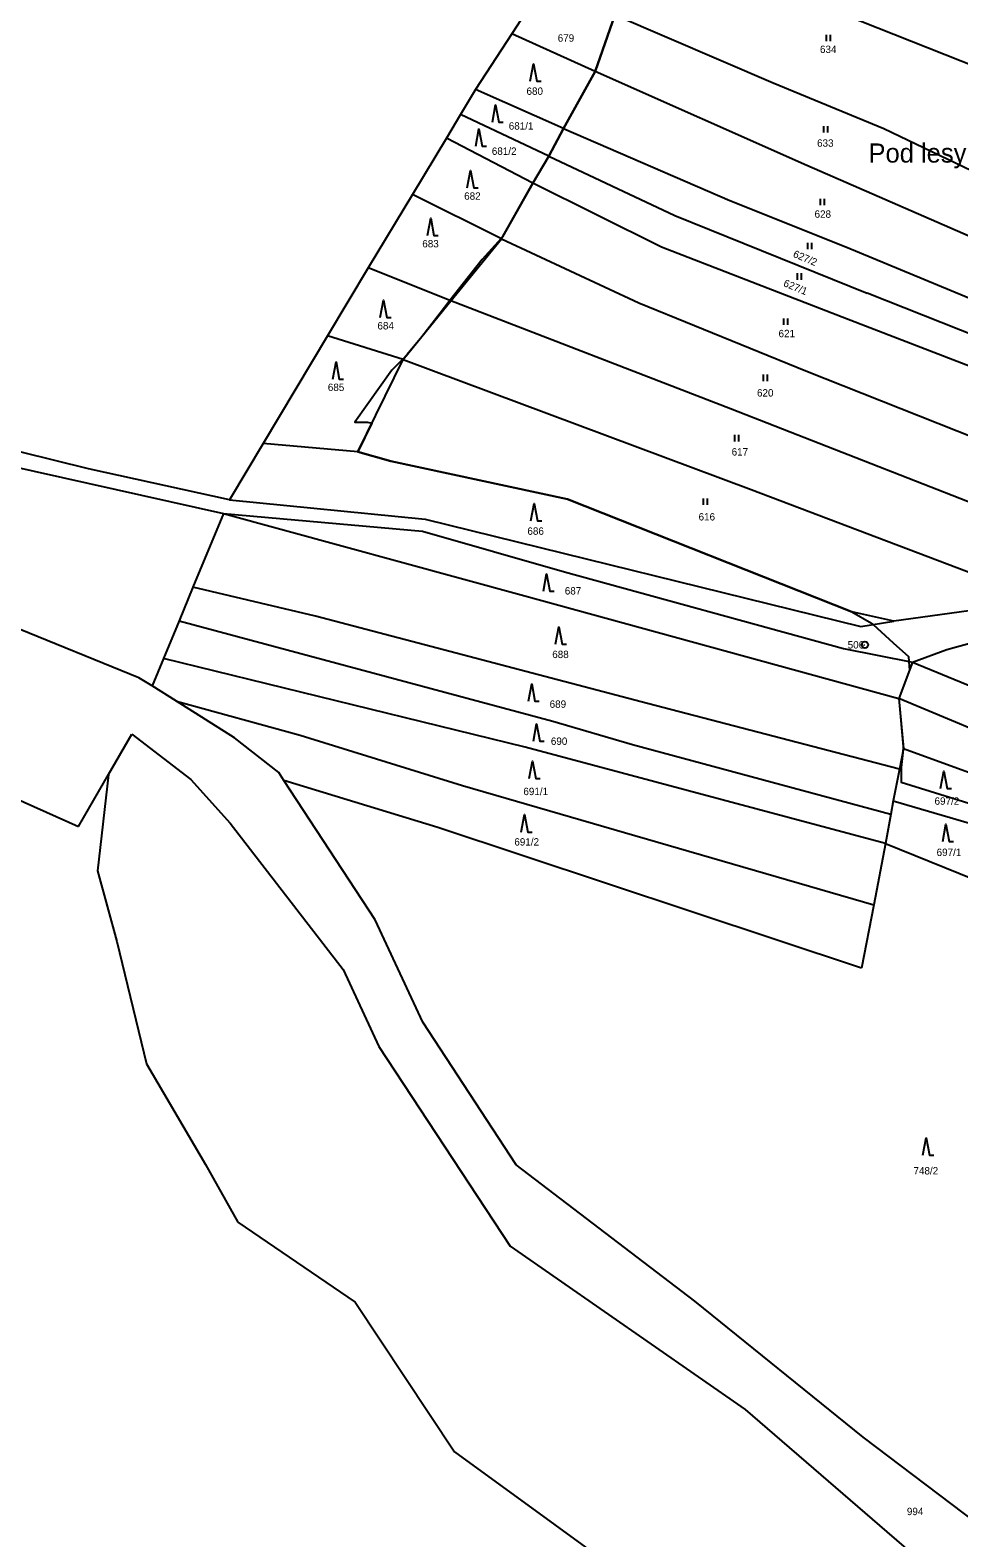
# Model space of a CAD drawing. Extents: x -749173 to -746119, y -1132678 to -1130338.
# Drawn here: x -748921.4 to -748707.5, y -1131207.1 to -1130859.8 of the extents above; entities that cross this region are included whole.
import ezdxf

# ---------------------------------------------------------------- set-up
doc = ezdxf.new("R2010")
doc.units = 0
for name, color, linetype in [('Vrstva 1', 7, 'Continuous'), ('Vrstva 15', 7, 'Continuous'), ('Vrstva 17', 7, 'Continuous'), ('Vrstva 18', 7, 'Continuous'), ('Vrstva 24', 7, 'Continuous'), ('Vrstva 25', 7, 'Continuous'), ('Vrstva 52', 7, 'Continuous'), ('Vrstva 6', 7, 'Continuous')]:
    doc.layers.add(name, color=color, linetype=linetype)

msp = doc.modelspace()

# ---------------------------------------------------------------- linework, layer by layer
at = {"layer": 'Vrstva 1'}
for points in [[(-748802.84, -1130848.91), (-748810.46, -1130860.65)], [(-748791.23, -1130869.37), (-748786.7, -1130856.35)], [(-748810.46, -1130860.65), (-748818.81, -1130873.52)], [(-748798.57, -1130882.46), (-748791.23, -1130869.37)], [(-748818.81, -1130873.52), (-748822.26, -1130879.25)], [(-748822.26, -1130879.25), (-748825.52, -1130884.67)], [(-748801.95, -1130888.88), (-748798.57, -1130882.46)], [(-748825.52, -1130884.67), (-748833.33, -1130897.65)], [(-748805.64, -1130895.06), (-748801.95, -1130888.88)], [(-748833.33, -1130897.65), (-748843.53, -1130914.6)], [(-748812.83, -1130907.88), (-748805.64, -1130895.06)], [(-748824.49, -1130922.2), (-748812.83, -1130907.88)], [(-748843.53, -1130914.6), (-748852.94, -1130930.24)], [(-748835.48, -1130935.7), (-748824.49, -1130922.2)], [(-748852.94, -1130930.24), (-748867.73, -1130955.03)], [(-748845.89, -1130956.91), (-748835.48, -1130935.7)], [(-748907.96, -1130960.85), (-748977.23, -1130943.74)], [(-748867.73, -1130955.03), (-748875.49, -1130968.04)], [(-748838.31, -1130959.08), (-748845.89, -1130956.91)], [(-748932.91, -1130958.6), (-748876.9, -1130971.17)], [(-748797.6, -1130967.82), (-748838.31, -1130959.08)], [(-748875.49, -1130968.04), (-748907.96, -1130960.85)], [(-748875.49, -1130968.04), (-748830.4, -1130972.44)], [(-748732.08, -1130993.78), (-748797.6, -1130967.82)], [(-748876.9, -1130971.17), (-748831.06, -1130975.19)], [(-748830.4, -1130972.44), (-748730.06, -1130997.2)], [(-748831.06, -1130975.19), (-748798.34, -1130984.6)], [(-748798.34, -1130984.6), (-748734.03, -1131002.28)], [(-748687.86, -1130991.16), (-748722.45, -1130995.95)], [(-748722.45, -1130995.95), (-748732.08, -1130993.78)], [(-748896.35, -1131008.97), (-748925.75, -1130997.04)], [(-748730.06, -1130997.2), (-748722.45, -1130995.95)], [(-748710.23, -1131002.5), (-748691.81, -1130997.44)], [(-748734.03, -1131002.28), (-748718.11, -1131005.41)], [(-748718.11, -1131005.41), (-748721.27, -1131013.77)], [(-748718.11, -1131005.41), (-748710.23, -1131002.5)], [(-748893.32, -1131010.83), (-748896.35, -1131008.97)], [(-748887.67, -1131014.39), (-748893.32, -1131010.83)], [(-748874.3, -1131022.82), (-748887.67, -1131014.39)], [(-748721.27, -1131013.77), (-748720.21, -1131025.25)], [(-748903.36, -1131031.29), (-748897.97, -1131021.96)], [(-748897.97, -1131021.96), (-748884.41, -1131032.45)], [(-748864.13, -1131030.78), (-748874.3, -1131022.82)], [(-748720.21, -1131025.25), (-748699.34, -1131032.91)], [(-748945.65, -1131027.42), (-748910.29, -1131043.26)], [(-748910.29, -1131043.26), (-748903.36, -1131031.29)], [(-748884.41, -1131032.45), (-748875.35, -1131042.49)], [(-748862.93, -1131032.61), (-748864.13, -1131030.78)], [(-748841.96, -1131064.7), (-748862.93, -1131032.61)], [(-748875.35, -1131042.49), (-748849.27, -1131076.16)], [(-748830.94, -1131088.32), (-748841.96, -1131064.7)], [(-748849.27, -1131076.16), (-748841.05, -1131093.93)], [(-748809.47, -1131121.13), (-748830.94, -1131088.32)], [(-748841.05, -1131093.93), (-748810.83, -1131139.93)], [(-748768.27, -1131152.58), (-748809.47, -1131121.13)], [(-748810.83, -1131139.93), (-748756.69, -1131177.5)], [(-748729.51, -1131183.85), (-748768.27, -1131152.58)], [(-748756.69, -1131177.5), (-748711.66, -1131216.37)], [(-748683.15, -1131218.97), (-748729.51, -1131183.85)]]:
    msp.add_lwpolyline(points, dxfattribs=at)
at = {"layer": 'Vrstva 24'}
msp.add_line((-748729.19, -1131001.4), (-748729.09, -1131001.4), dxfattribs=at)
msp.add_circle((-748729.14, -1131001.4), 0.756, dxfattribs=at)
at = {"layer": 'Vrstva 25'}
for p, q in [((-748738.05, -1130860.89), (-748738.05, -1130862.39)), ((-748737.05, -1130862.39), (-748737.05, -1130860.89)), ((-748738.64, -1130881.91), (-748738.64, -1130883.41)), ((-748737.64, -1130883.41), (-748737.64, -1130881.91)), ((-748739.41, -1130898.66), (-748739.41, -1130900.16)), ((-748738.41, -1130900.16), (-748738.41, -1130898.66)), ((-748742.3, -1130908.79), (-748742.3, -1130910.29)), ((-748741.3, -1130910.29), (-748741.3, -1130908.79)), ((-748744.71, -1130915.83), (-748744.71, -1130917.33)), ((-748743.71, -1130917.33), (-748743.71, -1130915.83)), ((-748747.86, -1130926.23), (-748747.86, -1130927.73)), ((-748746.86, -1130927.73), (-748746.86, -1130926.23)), ((-748752.55, -1130939.14), (-748752.55, -1130940.64)), ((-748751.55, -1130940.64), (-748751.55, -1130939.14)), ((-748759.11, -1130953.03), (-748759.11, -1130954.53)), ((-748758.11, -1130954.53), (-748758.11, -1130953.03)), ((-748766.4, -1130967.68), (-748766.4, -1130969.18)), ((-748765.4, -1130969.18), (-748765.4, -1130967.68))]:
    msp.add_line(p, q, dxfattribs=at)
for points in [[(-748806.2, -1130871.59), (-748805.45, -1130867.59), (-748804.7, -1130871.59), (-748803.7, -1130871.59)], [(-748814.92, -1130881.06), (-748814.17, -1130877.06), (-748813.42, -1130881.06), (-748812.42, -1130881.06)], [(-748818.76, -1130886.56), (-748818.01, -1130882.56), (-748817.26, -1130886.56), (-748816.26, -1130886.56)], [(-748820.7, -1130896.15), (-748819.95, -1130892.15), (-748819.2, -1130896.15), (-748818.2, -1130896.15)], [(-748829.89, -1130907.16), (-748829.14, -1130903.16), (-748828.39, -1130907.16), (-748827.39, -1130907.16)], [(-748840.74, -1130926.01), (-748839.99, -1130922.01), (-748839.24, -1130926.01), (-748838.24, -1130926.01)], [(-748851.69, -1130940.24), (-748850.94, -1130936.24), (-748850.19, -1130940.24), (-748849.19, -1130940.24)], [(-748806.04, -1130972.86), (-748805.29, -1130968.86), (-748804.54, -1130972.86), (-748803.54, -1130972.86)], [(-748803.17, -1130989.04), (-748802.42, -1130985.04), (-748801.67, -1130989.04), (-748800.67, -1130989.04)], [(-748800.38, -1131001.26), (-748799.63, -1130997.26), (-748798.88, -1131001.26), (-748797.88, -1131001.26)], [(-748806.62, -1131014.37), (-748805.87, -1131010.37), (-748805.12, -1131014.37), (-748804.12, -1131014.37)], [(-748805.48, -1131023.62), (-748804.73, -1131019.62), (-748803.98, -1131023.62), (-748802.98, -1131023.62)], [(-748806.45, -1131032.22), (-748805.7, -1131028.22), (-748804.95, -1131032.22), (-748803.95, -1131032.22)], [(-748711.67, -1131034.46), (-748710.92, -1131030.46), (-748710.17, -1131034.46), (-748709.17, -1131034.46)], [(-748808.29, -1131044.51), (-748807.54, -1131040.51), (-748806.79, -1131044.51), (-748805.79, -1131044.51)], [(-748711.18, -1131046.69), (-748710.43, -1131042.69), (-748709.68, -1131046.69), (-748708.68, -1131046.69)], [(-748715.72, -1131118.97), (-748714.97, -1131114.97), (-748714.22, -1131118.97), (-748713.22, -1131118.97)]]:
    msp.add_lwpolyline(points, dxfattribs=at)
at = {"layer": 'Vrstva 52'}
msp.add_lwpolyline([(-748786.7, -1130856.35), (-748791.23, -1130869.37), (-748798.57, -1130882.46), (-748801.95, -1130888.88), (-748805.64, -1130895.06), (-748812.58, -1130907.44), (-748812.62, -1130907.5), (-748812.93, -1130907.83), (-748817.31, -1130912.62), (-748824.71, -1130922.11), (-748826.97, -1130925.01), (-748831.19, -1130930.44), (-748834.52, -1130934.52), (-748835.65, -1130935.65), (-748838.12, -1130938.12), (-748846.62, -1130950.12), (-748843.69, -1130950.12), (-748842.68, -1130950.37), (-748845.89, -1130956.91), (-748838.31, -1130959.08), (-748797.6, -1130967.82), (-748732.08, -1130993.78), (-748727.56, -1130996.37), (-748727.4, -1130996.53), (-748727.18, -1130996.73), (-748722.57, -1131000.93), (-748719.06, -1131004.12), (-748718.96, -1131005.24), (-748718.79, -1131007.21), (-748721.27, -1131013.77), (-748720.25, -1131024.81), (-748720.39, -1131026.16), (-748720.75, -1131029.62), (-748720.75, -1131033), (-748699.74, -1131039.54)], dxfattribs=at)
at = {"layer": 'Vrstva 6'}
for points in [[(-748750.23, -1130872.02), (-748786.7, -1130856.35)], [(-748733.87, -1130856.25), (-748691.38, -1130873.01)], [(-748791.23, -1130869.37), (-748810.46, -1130860.65)], [(-748742.5, -1130891), (-748791.23, -1130869.37)], [(-748798.57, -1130882.46), (-748818.81, -1130873.52)], [(-748724.77, -1130882.55), (-748750.23, -1130872.02)], [(-748801.95, -1130888.88), (-748822.26, -1130879.25)], [(-748798.57, -1130882.46), (-748760.2, -1130899.08)], [(-748691.56, -1130898.44), (-748724.77, -1130882.55)], [(-748805.64, -1130895.06), (-748825.52, -1130884.67)], [(-748801.95, -1130888.88), (-748772.9, -1130902.53)], [(-748676.59, -1130919.71), (-748742.5, -1130891)], [(-748812.83, -1130907.88), (-748833.33, -1130897.65)], [(-748775.96, -1130909.83), (-748805.64, -1130895.06)], [(-748760.2, -1130899.08), (-748733.51, -1130909.72)], [(-748772.9, -1130902.53), (-748728.61, -1130920.39)], [(-748812.83, -1130907.88), (-748781.18, -1130922.64)], [(-748734.35, -1130925.92), (-748775.96, -1130909.83)], [(-748733.51, -1130909.72), (-748702.92, -1130922.4)], [(-748824.49, -1130922.2), (-748843.53, -1130914.6)], [(-748760.05, -1130947.07), (-748824.49, -1130922.2)], [(-748672.59, -1130942.59), (-748728.61, -1130920.39)], [(-748781.18, -1130922.64), (-748742.72, -1130938.33)], [(-748673.99, -1130949.21), (-748734.35, -1130925.92)], [(-748835.48, -1130935.7), (-748852.94, -1130930.24)], [(-748835.48, -1130935.7), (-748755.34, -1130965.63)], [(-748742.72, -1130938.33), (-748677.43, -1130964.14)], [(-748686.82, -1130975.66), (-748760.05, -1130947.07)], [(-748845.89, -1130956.91), (-748867.73, -1130955.03)], [(-748755.34, -1130965.63), (-748687.86, -1130991.16)], [(-748876.9, -1130971.17), (-748883.92, -1130988.13)], [(-748876.9, -1130971.17), (-748808.26, -1130989.85)], [(-748883.92, -1130988.13), (-748887.11, -1130995.84)], [(-748855.69, -1130994.76), (-748883.92, -1130988.13)], [(-748808.26, -1130989.85), (-748721.27, -1131013.77)], [(-748779.2, -1131014.91), (-748855.69, -1130994.76)], [(-748887.11, -1130995.84), (-748890.71, -1131004.53)], [(-748887.11, -1130995.84), (-748800.99, -1131019)], [(-748890.71, -1131004.53), (-748893.32, -1131010.83)], [(-748807.39, -1131024.98), (-748890.71, -1131004.53)], [(-748718.11, -1131005.41), (-748691.78, -1131016.23)], [(-748887.67, -1131014.39), (-748859.22, -1131022.19)], [(-748721.16, -1131030.03), (-748779.2, -1131014.91)], [(-748691.89, -1131026.01), (-748721.27, -1131013.77)], [(-748800.99, -1131019), (-748782.66, -1131024.35)], [(-748859.22, -1131022.19), (-748821.78, -1131033.78)], [(-748724.39, -1131047.18), (-748807.39, -1131024.98)], [(-748782.66, -1131024.35), (-748723.16, -1131040.37)], [(-748720.21, -1131025.25), (-748721.16, -1131030.03)], [(-748721.16, -1131030.03), (-748722.61, -1131037.34)], [(-748903.36, -1131031.29), (-748905.89, -1131053.47)], [(-748827.51, -1131043.45), (-748862.93, -1131032.61)], [(-748821.78, -1131033.78), (-748727.08, -1131061.25)], [(-748723.16, -1131040.37), (-748724.39, -1131047.18)], [(-748722.61, -1131037.34), (-748723.16, -1131040.37)], [(-748722.61, -1131037.34), (-748700.01, -1131043.9)], [(-748729.9, -1131075.88), (-748827.51, -1131043.45)], [(-748724.39, -1131047.18), (-748727.08, -1131061.25)], [(-748724.39, -1131047.18), (-748700.66, -1131056.76)], [(-748905.89, -1131053.47), (-748901.45, -1131069.76)], [(-748727.08, -1131061.25), (-748729.9, -1131075.88)], [(-748901.45, -1131069.76), (-748894.6, -1131097.89)], [(-748894.6, -1131097.89), (-748881.04, -1131121.08)], [(-748881.04, -1131121.08), (-748873.58, -1131134.34)], [(-748873.58, -1131134.34), (-748846.57, -1131152.8)], [(-748846.57, -1131152.8), (-748823.65, -1131187.26)], [(-748823.65, -1131187.26), (-748755.15, -1131237.08)]]:
    msp.add_lwpolyline(points, dxfattribs=at)

# ---------------------------------------------------------------- texts
at = {"layer": 'Vrstva 15'}
msp.add_text('Pod lesy', height=4.4, dxfattribs=at).set_placement((-748728.28, -1130890.33))
at = {"layer": 'Vrstva 17'}
msp.add_text('506', height=1.7, dxfattribs=at).set_placement((-748733.07, -1131002.25))
at = {"layer": 'Vrstva 18'}
for s, p in [('679', (-748799.87, -1130862.49)), ('634', (-748739.45, -1130865.09)), ('680', (-748807.06, -1130874.73)), ('681/1', (-748811.15, -1130882.74)), ('681/2', (-748815.05, -1130888.55)), ('633', (-748740.12, -1130886.68)), ('682', (-748821.42, -1130898.89)), ('628', (-748740.7, -1130903.04)), ('683', (-748831.07, -1130909.86)), ('684', (-748841.4, -1130928.76)), ('621', (-748749, -1130930.55)), ('685', (-748852.83, -1130942.94)), ('620', (-748753.96, -1130944.21)), ('617', (-748759.8, -1130957.8)), ('616', (-748767.42, -1130972.76)), ('686', (-748806.85, -1130976.05)), ('687', (-748798.24, -1130989.81)), ('688', (-748801.13, -1131004.45)), ('689', (-748801.73, -1131015.9)), ('690', (-748801.45, -1131024.44)), ('691/1', (-748807.78, -1131036.01)), ('697/2', (-748713.06, -1131038.23)), ('691/2', (-748809.86, -1131047.63)), ('697/1', (-748712.58, -1131050.03)), ('748/2', (-748717.91, -1131123.38)), ('994', (-748719.43, -1131201.84))]:
    msp.add_text(s, height=1.7, dxfattribs=at).set_placement(p)
for s, rotation, p in [('627/2', 337.2316, (-748745.81, -1130912)), ('627/1', 337.6479, (-748748.04, -1130918.73))]:
    msp.add_text(s, height=1.7, rotation=rotation, dxfattribs=at).set_placement(p)

doc.saveas('drawing.dxf')
